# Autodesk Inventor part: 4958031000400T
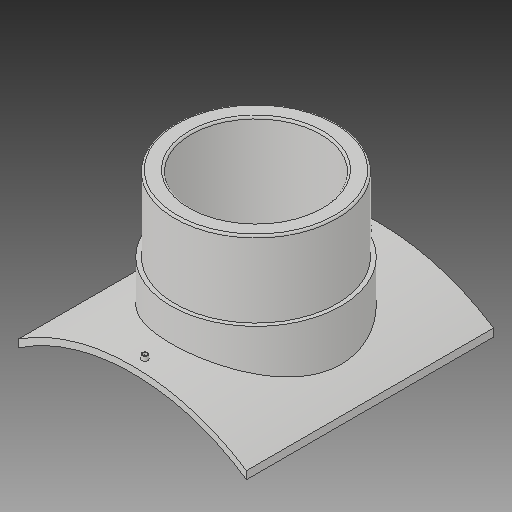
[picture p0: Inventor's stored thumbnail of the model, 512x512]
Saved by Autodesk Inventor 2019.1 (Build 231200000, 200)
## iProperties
Created: 2017-10
Part Number: 4958031000400T
Material: Generic
Description: PLASSON BRANCH SADDLE 1000x400
Document SubType Name: Modeling
Designer: KIM
Mass: 2754.05 g
Surface Area: 3037.44 cm^2
Volume: 2754.05 cm^3
Density: 1 g/cm^3
Appearance: Default
Author: KIM
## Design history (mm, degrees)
derived "495803.ipt"
feature "Solid1::495803.ipt"
tag "TaggingFeature1"
body "Solid1"
other parameters: "d1" = 16, "d2" = 563, "d4" = 0, "d12" = 525.6, "d13" = 14, "d14" = 274.5, "d16" = 5 deg, "d18" = 4, "d19" = 14, "d20" = 0, "d21" = 3, "d22" = 0, "d23" = 783, "d25" = 16, "d28" = 0, "d29" = 9.6, "d31" = 0, "d32" = 133.5, "d33" = 0, "d37" = 186.9, "d38" = 0, "d39" = 5, "B_" = 563, "H_" = 267, "x_" = 16, "D_" = 16
